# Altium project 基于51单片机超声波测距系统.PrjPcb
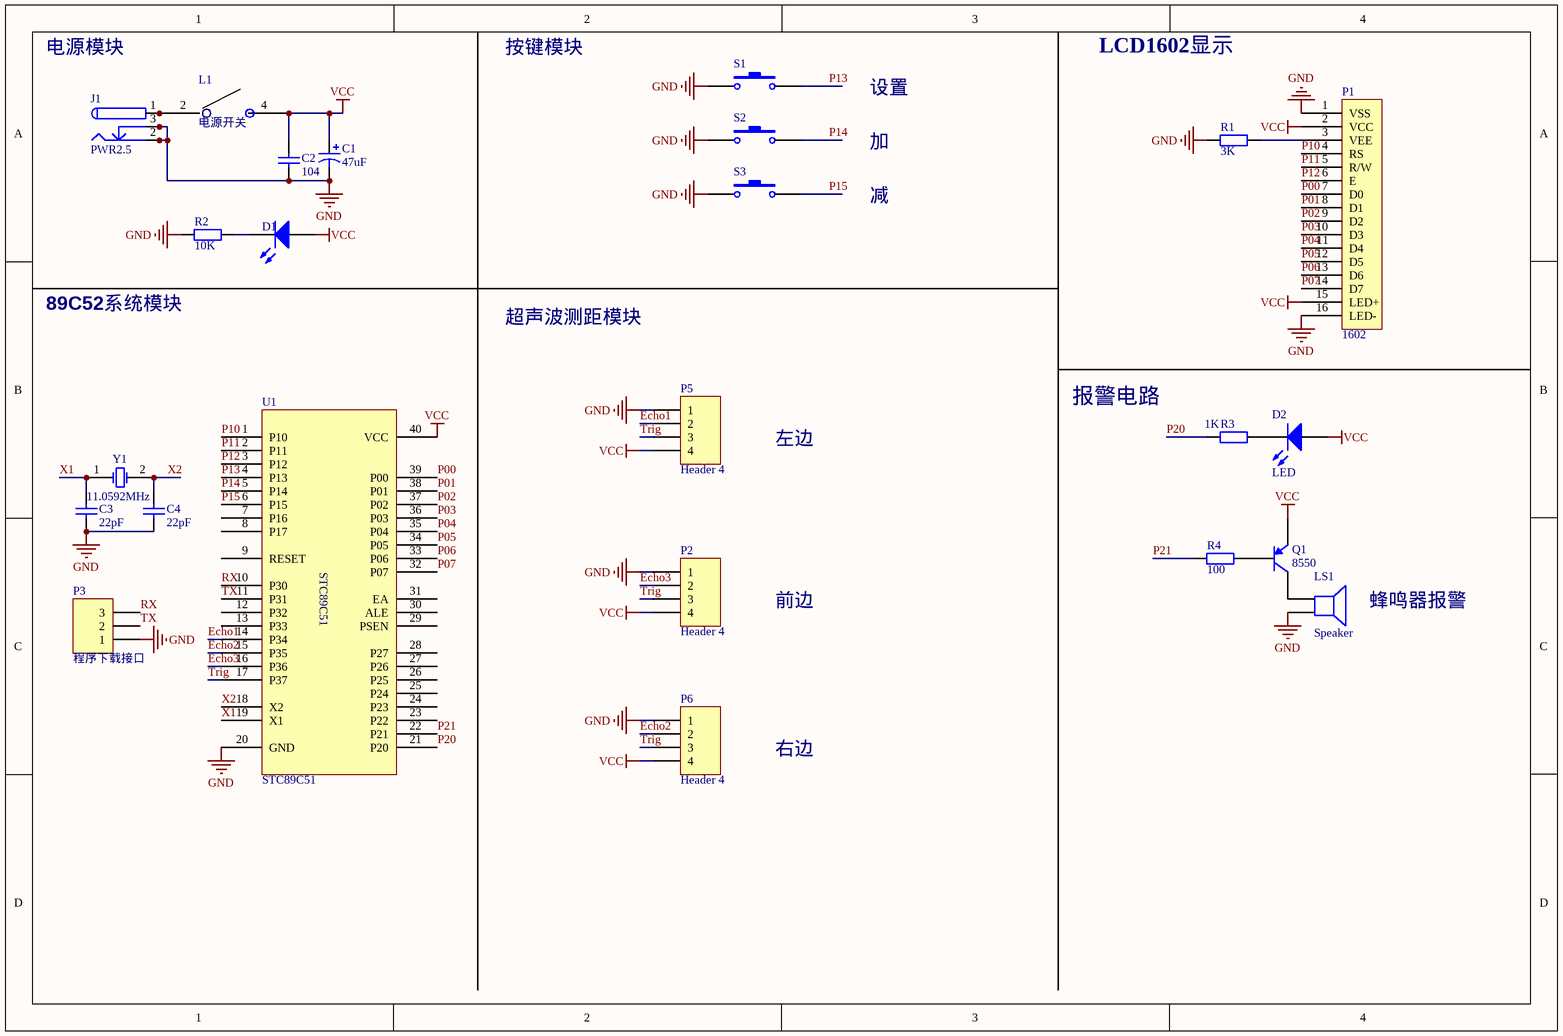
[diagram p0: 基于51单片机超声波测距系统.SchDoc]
1 sheet, 24 parts. Net scope: global (net labels, ports and power ports of the same name join across sheets).
Board file: 基于51单片机超声波测距系统.PcbDoc

## Sheet 基于51单片机超声波测距系统.SchDoc
size A4

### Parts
C1  47uF  [电解电容]
C2  104  [瓷片电容]
C3  22pF  [瓷片电容]
C4  22pF  [瓷片电容]
D1  LED  [发光二极管]  (value not drawn)
D2  LED  [发光二极管]
J1  PWR2.5  [电源接头]
L1  电源开关  [开关]
LS1  Speaker  [蜂鸣器]
P1  1602  [LCD1602液晶]
P2  Header 4  [4P座]
P3  程序下载接口  [下载器]
P5  Header 4  [4P座]
P6  Header 4  [4P座]
Q1  8550  [三极管]
R1  3K  [电阻]
R2  10K  [电阻]
R3  1K  [电阻]
R4  100  [电阻]
S1  (no value)  [按键]
S2  (no value)  [按键]
S3  (no value)  [按键]
U1  STC89C51  [51单片机]
Y1  11.0592MHz  [晶振]

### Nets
GND: C1.2 C2.1 C3.1 C4.1 J1.2 J1.2A J1.2B J1.3 J1.3A J1.3B LS1.2 P1.1(VSS) P1.16(LED-) P2.1 P3.1 P5.1 P6.1 R1.1 R2.1 S1.1 S2.1 S3.1 U1.20(GND)
VCC: C1.1 C2.2 D1.1(A) D2.1(A) L1.4 P1.2(VCC) P1.15(LED+) P2.4 P5.4 P6.4 Q1.1(E) U1.40(VCC)
Echo1: P5.2 U1.14(P34)
Echo2: P6.2 U1.15(P35)
Echo3: P2.2 U1.16(P36)
P00: P1.7(D0) U1.39(P00)
P01: P1.8(D1) U1.38(P01)
P02: P1.9(D2) U1.37(P02)
P03: P1.10(D3) U1.36(P03)
P04: P1.11(D4) U1.35(P04)
P05: P1.12(D5) U1.34(P05)
P06: P1.13(D6) U1.33(P06)
P07: P1.14(D7) U1.32(P07)
P10: P1.4(RS) U1.1(P10)
P11: P1.5(R/W) U1.2(P11)
P12: P1.6(E) U1.3(P12)
P13: S1.2 U1.4(P13)
P14: S2.2 U1.5(P14)
P15: S3.2 U1.6(P15)
P20: R3.1 U1.21(P20)
P21: R4.1 U1.22(P21)
RX: P3.3 U1.10(P30)
Trig: P2.3 P5.3 P6.3 U1.17(P37)
TX: P3.2 U1.11(P31)
X1: C3.2 U1.19(X1) Y1.1(OSC1)
X2: C4.2 U1.18(X2) Y1.2(OSC2)
NetD1_2: D1.2(K) R2.2
NetD2_2: D2.2(K) R3.2
NetJ1_1: J1.1 J1.1A J1.1B L1.2
NetLS1_1: LS1.1 Q1.3(C)
NetP1_3: P1.3(VEE) R1.2
NetQ1_2: Q1.2(B) R4.2

Not connected (* = marked no-connect by the designer): U1 7(P16) 8(P17) 9(RESET) 12(P32) 13(P33) 23(P22) 24(P23) 25(P24) 26(P25) 27(P26) 28(P27) 29(PSEN) 30(ALE) 31(EA)

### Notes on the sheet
- 电源模块
- 按键模块
- 设置
- LCD1602显示
- 加
- 减
- 89C52系统模块
- 超声波测距模块
- 左边
- 报警电路
- 前边
- 蜂鸣器报警
- 右边

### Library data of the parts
C1 = Cap Pol1: Polarized Capacitor (Radial)
C2-C4 = Cap: Capacitor
D1 D2 = LED0: Typical INFRARED GaAs LED
J1 = PWR2.5: Low Voltage Power Supply Connector
L1 = Liujiao
LS1 = Speaker: Loudspeaker
P2 P5 P6 = Header 4: Header, 4-Pin
P3 = Header 3: Header, 3-Pin
Q1 = 2N3906: PNP General Purpose Amplifier
R1-R4 = Res2: Resistor
S1-S3 = SW-PB: Switch
U1 = STC89C52
Y1 = XTAL: Crystal Oscillator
